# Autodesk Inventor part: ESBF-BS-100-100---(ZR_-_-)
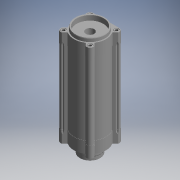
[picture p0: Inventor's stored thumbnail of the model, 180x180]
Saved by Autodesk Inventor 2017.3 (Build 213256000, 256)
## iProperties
Part Number: ESBF-BS-100-100---(ZR_-_-)
Material: Generic
Catalog Web Link: www.cadenas.de
Description: ESBF-(ZR)-Electro-cylinder
Vendor: FESTO
Document SubType Name: Modeling
Designer: partserver
Manufacturer: FESTO
Mass: 2150.83 g
Surface Area: 3014.64 cm^2
Volume: 2150.83 cm^3
Density: 1 g/cm^3
Appearance: PSOLRGB-192-192-192
Category: PARTsolutions
Company: FESTO
Title: ESBF-BS-100-100---(ZR_-_-)
Author: Cadenas PARTsolutions
Comments: Electro-cylinder
PSOL_IDENT_0: {$CADENAS_DATA\23d-libs\festo\parts\e\esbf\parts\esbf_zr.prj},210 {VTYP=3D},{NB=ESBF-BS-100-100---(Z
PSOL_IDENT_1: R_-_-)},{LINA=ESBF-BS-100-100---(ZR_-_-)},{NN=ESBF-(ZR)},{DATE=27.05.2021 13:20:18},{GEOMDATE=27.05.
PSOL_IDENT_2: 2021 13:19:59},{VERSION=},{LINEID=30},{WBVAR=HUB,SCEL,BWE},{WBNUMERIC=HUB}  {NB=ESBF-BS-100-100---(Z
PSOL_IDENT_3: R_-_-)},{LINA=ESBF-BS-100-100---(ZR_-_-)},{KT=DUMMY},{TNR=574092},{TYP=ESBF-BS-100},{KDM=100},{HUB=1
PSOL_IDENT_4: 00},{SCEL=-},{BWE=-},{A=29.000},{ANG=45.000},{B=70.000},{B1=68.000},{BE1=18.000},{BG=17.000},{D1=50.
PSOL_IDENT_5: 000},{D2=24.000},{D2R=15.000},{D3=100.000},{D3R=15.800},{D5=90.000},{E=110.000},{E1=0.000},{EG=20.50
PSOL_IDENT_6: 0},{G=39.000},{G1=39.000},{HE=4.000},{R1=10.500},{R1I=10.000},{R2=107.600},{TG=89.000},{RI=53.250},{
PSOL_IDENT_7: RK=1.500},{T5=16.500},{J2=0.000},{L10=21.000},{L14=30.000},{L16=20.200},{L18=0.000},{L1=33.000},{L2=
PSOL_IDENT_8: 224.000},{L3=39.500},{L7=68.500},{M1=10.000},{PL=0.000},{SW3=6.000},{SWT=25.900},{VA=12.000},{VD=20.
PSOL_IDENT_9: 000},{D100=0.000},{GUA=28.000},{B2=5.000},{D6=51.500},{D7=61.200},{BWE1='-','F1A'}
NB: ESBF-BS-100-100---(ZR_-_-)
NN: ESBF-(ZR)
NT: Electro-cylinder
NBSYN: $TYP.-$HUB.---(ZR_$SCEL._$BWE.)
LINA: ESBF-BS-100-100---(ZR_-_-)
CATALOG: Festo
TNR: 574092
TYP: ESBF-BS-100
KDM: 100
HUB: 100
SCEL: -
BWE: -
A: 29
ANG: 45
B: 70
B1: 68
BE1: 18
BG: 17
D1: 50
D2: 24
D2R: 15
D3: 100
D3R: 15.8
D5: 90
E: 110
E1: 0
EG: 20.5
G: 39
G1: 39
HE: 4
R1: 10.5
R1I: 10
R2: 107.6
TG: 89
RI: 53.25
RK: 1.5
T5: 16.5
J2: 0
L10: 21
L14: 30
L16: 20.2
L18: 0
L1: 33
L2: 224
L3: 39.5
L7: 68.5
M1: 10
PL: 0
SW3: 6
SWT: 25.9
VA: 12
VD: 20
D100: 0
GUA: 28
B2: 5
D6: 51.5
D7: 61.2
SUPPLIER: FESTO
ARTICLENO: ESBF-BS-100-100---(ZR_-_-)
BOMINFO: ESBF-BS-100-100---(ZR_-_-)
CREATOR: CADENAS GmbH
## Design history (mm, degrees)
sketch "Sketch_1"
  geometry: L1 (-54.561, 39.711)-(-45.596, 30.747); L2 (-45.596, -30.747)-(-54.561, -39.711); L3 (-55, -40.772)-(-55, -44.5); L4 (-44.5, -55)-(-40.772, -55); L5 (-39.711, -54.561)-(-30.747, -45.596); L6 (30.747, -45.596)-(39.711, -54.561); L7 (40.772, -55)-(44.5, -55); L8 (55, -44.5)-(55, -40.772); L9 (54.561, -39.711)-(45.596, -30.747); L10 (45.596, 30.747)-(54.561, 39.711); L11 (55, 40.772)-(55, 44.5); L12 (44.5, 55)-(-44.5, 55); L13 (-55, 44.5)-(-55, 40.772); A1 r 1.5 centre (-53.5, 40.772) between (-55, 40.772) and (-54.561, 39.711); A2 r 1.5 centre (-46.657, 29.686) between (-45.391, 28.881) and (-45.596, 30.747); A3 r 53.8 centre (0, 0) between (-45.391, 28.881) and (-45.391, -28.881); A4 r 1.5 centre (-46.657, -29.686) between (-45.596, -30.747) and (-45.391, -28.881); A5 r 1.5 centre (-53.5, -40.772) between (-54.561, -39.711) and (-55, -40.772); A6 r 10.5 centre (-44.5, -44.5) between (-55, -44.5) and (-44.5, -55); A7 r 1.5 centre (-40.772, -53.5) between (-40.772, -55) and (-39.711, -54.561); A8 r 1.5 centre (-29.686, -46.657) between (-28.881, -45.391) and (-30.747, -45.596); A9 r 53.8 centre (0, 0) between (-28.881, -45.391) and (28.881, -45.391); A10 r 1.5 centre (29.686, -46.657) between (30.747, -45.596) and (28.881, -45.391); A11 r 1.5 centre (40.772, -53.5) between (39.711, -54.561) and (40.772, -55); A12 r 10.5 centre (44.5, -44.5) between (44.5, -55) and (55, -44.5); A13 r 1.5 centre (53.5, -40.772) between (55, -40.772) and (54.561, -39.711); A14 r 1.5 centre (46.657, -29.686) between (45.391, -28.881) and (45.596, -30.747); A15 r 53.8 centre (0, 0) between (45.391, -28.881) and (45.391, 28.881); A16 r 1.5 centre (46.657, 29.686) between (45.596, 30.747) and (45.391, 28.881); A17 r 1.5 centre (53.5, 40.772) between (54.561, 39.711) and (55, 40.772); A18 r 10.5 centre (44.5, 44.5) between (55, 44.5) and (44.5, 55); A19 r 10.5 centre (-44.5, 44.5) between (-44.5, 55) and (-55, 44.5)
  constraints: 38 point on circle, 26 end point, 19 centre point
extrude "Extrusion1" join sketch "Sketch_1" distance "d0" = 39; taper "d1" = 0 deg
sketch "Sketch_8"
  geometry: L1 (-50, 73)-(50, 73); L2 (-41.5, 68.75)-(-41.5, 55); L3 (-41.5, 55)-(-39.248, 51.1); L4 (-39.075, 51)-(-38.373, 51); L5 (-38.232, 51.059)-(-34.291, 55); L6 (-34.291, 55)-(34.291, 55); L7 (34.291, 55)-(38.232, 51.059); L8 (38.373, 51)-(39.075, 51); L9 (39.248, 51.1)-(41.5, 55); L10 (41.5, 55)-(41.5, 68.75); L11 (41.5, 68.75)-(-41.5, 68.75); A1 r 0.2 centre (-39.075, 51.2) between (-39.248, 51.1) and (-39.075, 51); A2 r 0.2 centre (-38.373, 51.2) between (-38.373, 51) and (-38.232, 51.059); A3 r 0.2 centre (38.373, 51.2) between (38.232, 51.059) and (38.373, 51); A4 r 0.2 centre (39.075, 51.2) between (39.075, 51) and (39.248, 51.1)
  constraints: 22 end point, 8 point on circle, 4 centre point
revolve "Revolution1" sketch "Sketch_8" stored, may be unused: angle "d2" = 360 deg
sketch "Sketch_21"
  geometry: L1 (50, -74)-(-50, -74); L2 (-41.5, -68.75)-(41.5, -68.75); L3 (41.5, -68.75)-(41.5, -55); L4 (41.5, -55)-(39.248, -51.1); L5 (39.075, -51)-(25.005, -51); L6 (-25.005, -51)-(-39.075, -51); L7 (-39.248, -51.1)-(-41.5, -55); L8 (-41.5, -55)-(-41.5, -68.75); A1 r 0.2 centre (39.075, -51.2) between (39.248, -51.1) and (39.075, -51); A2 r 56.8 centre (0, 0) between (-25.005, -51) and (25.005, -51); A3 r 0.2 centre (-39.075, -51.2) between (-39.075, -51) and (-39.248, -51.1)
  constraints: 16 end point, 6 point on circle, 3 centre point
revolve "Revolution2" sketch "Sketch_21" stored, may be unused: angle "d3" = 360 deg
sketch "Sketch_23"
  geometry: L1 (74, 50)-(74, -50); L2 (51, -25.005)-(51, -39.075); L3 (51.1, -39.248)-(55, -41.5); L4 (55, -41.5)-(68.75, -41.5); L5 (68.75, -41.5)-(68.75, 41.5); L6 (68.75, 41.5)-(55, 41.5); L7 (55, 41.5)-(51.1, 39.248); L8 (51, 39.075)-(51, 25.005); A1 r 0.2 centre (51.2, -39.075) between (51, -39.075) and (51.1, -39.248); A2 r 0.2 centre (51.2, 39.075) between (51.1, 39.248) and (51, 39.075); A3 r 56.8 centre (0, 0) between (51, -25.005) and (51, 25.005)
  constraints: 16 end point, 6 point on circle, 3 centre point
revolve "Revolution3" sketch "Sketch_23" stored, may be unused: angle "d4" = 360 deg
sketch "Sketch_24"
  geometry: L1 (-74, -50)-(-74, 50); L2 (-68.75, -41.5)-(-55, -41.5); L3 (-55, -41.5)-(-51.1, -39.248); L4 (-51, -39.075)-(-51, -25.005); L5 (-51, 25.005)-(-51, 39.075); L6 (-51.1, 39.248)-(-55, 41.5); L7 (-55, 41.5)-(-68.75, 41.5); L8 (-68.75, 41.5)-(-68.75, -41.5); A1 r 0.2 centre (-51.2, -39.075) between (-51.1, -39.248) and (-51, -39.075); A2 r 56.8 centre (0, 0) between (-51, 25.005) and (-51, -25.005); A3 r 0.2 centre (-51.2, 39.075) between (-51, 39.075) and (-51.1, 39.248)
  constraints: 16 end point, 6 point on circle, 3 centre point
revolve "Revolution4" sketch "Sketch_24" stored, may be unused: angle "d5" = 360 deg
sketch "Sketch_41"
  geometry: L1 (0, -285)-(0, -39); L2 (0, -39)-(5, -39); L3 (5, -39)-(5, -285); L4 (5, -285)-(0, -285); L5 (0, -285)-(0, -39)
  constraints: 10 end point
revolve "Revolution5" sketch "Sketch_41" stored, may be unused: angle "d6" = 360 deg
sketch "Sketch_5"
  geometry: L1 (-54.561, 39.711)-(-45.596, 30.747); L2 (-45.596, -30.747)-(-54.561, -39.711); L3 (-55, -40.772)-(-55, -44.5); L4 (-44.5, -55)-(-40.772, -55); L5 (-39.711, -54.561)-(-30.747, -45.596); L6 (30.747, -45.596)-(39.711, -54.561); L7 (40.772, -55)-(44.5, -55); L8 (55, -44.5)-(55, -40.772); L9 (54.561, -39.711)-(45.596, -30.747); L10 (45.596, 30.747)-(54.561, 39.711); L11 (55, 40.772)-(55, 44.5); L12 (44.5, 55)-(-44.5, 55); L13 (-55, 44.5)-(-55, 40.772); A1 r 1.5 centre (-53.5, 40.772) between (-55, 40.772) and (-54.561, 39.711); A2 r 1.5 centre (-46.657, 29.686) between (-45.391, 28.881) and (-45.596, 30.747); A3 r 53.8 centre (0, 0) between (-45.391, 28.881) and (-45.391, -28.881); A4 r 1.5 centre (-46.657, -29.686) between (-45.596, -30.747) and (-45.391, -28.881); A5 r 1.5 centre (-53.5, -40.772) between (-54.561, -39.711) and (-55, -40.772); A6 r 10.5 centre (-44.5, -44.5) between (-55, -44.5) and (-44.5, -55); A7 r 1.5 centre (-40.772, -53.5) between (-40.772, -55) and (-39.711, -54.561); A8 r 1.5 centre (-29.686, -46.657) between (-28.881, -45.391) and (-30.747, -45.596); A9 r 53.8 centre (0, 0) between (-28.881, -45.391) and (28.881, -45.391); A10 r 1.5 centre (29.686, -46.657) between (30.747, -45.596) and (28.881, -45.391); A11 r 1.5 centre (40.772, -53.5) between (39.711, -54.561) and (40.772, -55); A12 r 10.5 centre (44.5, -44.5) between (44.5, -55) and (55, -44.5); A13 r 1.5 centre (53.5, -40.772) between (55, -40.772) and (54.561, -39.711); A14 r 1.5 centre (46.657, -29.686) between (45.391, -28.881) and (45.596, -30.747); A15 r 53.8 centre (0, 0) between (45.391, -28.881) and (45.391, 28.881); A16 r 1.5 centre (46.657, 29.686) between (45.596, 30.747) and (45.391, 28.881); A17 r 1.5 centre (53.5, 40.772) between (54.561, 39.711) and (55, 40.772); A18 r 10.5 centre (44.5, 44.5) between (55, 44.5) and (44.5, 55); A19 r 10.5 centre (-44.5, 44.5) between (-44.5, 55) and (-55, 44.5)
  constraints: 38 point on circle, 26 end point, 19 centre point
extrude "Extrusion2" join sketch "Sketch_5" distance "d7" = 39; taper "d8" = 0 deg
sketch "Sketch_4"
  geometry: L1 (-50, 74)-(50, 74); L2 (-41.5, 68.75)-(-41.5, 55); L3 (-41.5, 55)-(-39.248, 51.1); L4 (-39.075, 51)-(-38.373, 51); L5 (-38.232, 51.059)-(-34.291, 55); L6 (-34.291, 55)-(34.291, 55); L7 (34.291, 55)-(38.232, 51.059); L8 (38.373, 51)-(39.075, 51); L9 (39.248, 51.1)-(41.5, 55); L10 (41.5, 55)-(41.5, 68.75); L11 (41.5, 68.75)-(-41.5, 68.75); A1 r 0.2 centre (-39.075, 51.2) between (-39.248, 51.1) and (-39.075, 51); A2 r 0.2 centre (-38.373, 51.2) between (-38.373, 51) and (-38.232, 51.059); A3 r 0.2 centre (38.373, 51.2) between (38.232, 51.059) and (38.373, 51); A4 r 0.2 centre (39.075, 51.2) between (39.075, 51) and (39.248, 51.1)
  constraints: 22 end point, 8 point on circle, 4 centre point
revolve "Revolution6" sketch "Sketch_4" stored, may be unused: angle "d9" = 360 deg
sketch "Sketch_25"
  geometry: L1 (50, -74)-(-50, -74); L2 (-41.5, -73.333)-(41.5, -73.333); L3 (41.5, -73.333)-(41.5, -55); L4 (41.5, -55)-(39.248, -51.1); L5 (39.075, -51)-(25.005, -51); L6 (-25.005, -51)-(-39.075, -51); L7 (-39.248, -51.1)-(-41.5, -55); L8 (-41.5, -55)-(-41.5, -73.333); A1 r 0.2 centre (39.075, -51.2) between (39.248, -51.1) and (39.075, -51); A2 r 56.8 centre (0, 0) between (-25.005, -51) and (25.005, -51); A3 r 0.2 centre (-39.075, -51.2) between (-39.075, -51) and (-39.248, -51.1)
  constraints: 16 end point, 6 point on circle, 3 centre point
revolve "Revolution7" sketch "Sketch_25" stored, may be unused: angle "d10" = 360 deg
sketch "Sketch_26"
  geometry: L1 (74, 50)-(74, -50); L2 (51, -25.005)-(51, -39.075); L3 (51.1, -39.248)-(55, -41.5); L4 (55, -41.5)-(68.75, -41.5); L5 (68.75, -41.5)-(68.75, 41.5); L6 (68.75, 41.5)-(55, 41.5); L7 (55, 41.5)-(51.1, 39.248); L8 (51, 39.075)-(51, 25.005); A1 r 0.2 centre (51.2, -39.075) between (51, -39.075) and (51.1, -39.248); A2 r 0.2 centre (51.2, 39.075) between (51.1, 39.248) and (51, 39.075); A3 r 56.8 centre (0, 0) between (51, -25.005) and (51, 25.005)
  constraints: 16 end point, 6 point on circle, 3 centre point
revolve "Revolution8" sketch "Sketch_26" stored, may be unused: angle "d11" = 360 deg
sketch "Sketch_27"
  geometry: L1 (-74, -50)-(-74, 50); L2 (-68.75, -41.5)-(-55, -41.5); L3 (-55, -41.5)-(-51.1, -39.248); L4 (-51, -39.075)-(-51, -25.005); L5 (-51, 25.005)-(-51, 39.075); L6 (-51.1, 39.248)-(-55, 41.5); L7 (-55, 41.5)-(-68.75, 41.5); L8 (-68.75, 41.5)-(-68.75, -41.5); A1 r 0.2 centre (-51.2, -39.075) between (-51.1, -39.248) and (-51, -39.075); A2 r 56.8 centre (0, 0) between (-51, 25.005) and (-51, -25.005); A3 r 0.2 centre (-51.2, 39.075) between (-51, 39.075) and (-51.1, 39.248)
  constraints: 16 end point, 6 point on circle, 3 centre point
revolve "Revolution9" sketch "Sketch_27" stored, may be unused: angle "d12" = 360 deg
sketch "Sketch_43"
  geometry: L1 (-41.679, -54.155)-(-39.828, -50.95); L2 (-39.482, -50.75)-(-36.42, -50.75); L3 (-36.137, -50.633)-(-30.564, -45.06); L4 (30.564, -45.06)-(36.137, -50.633); L5 (36.42, -50.75)-(39.482, -50.75); L6 (39.828, -50.95)-(41.679, -54.155); L7 (54.155, -41.679)-(50.95, -39.828); L8 (50.75, -39.482)-(50.75, -36.42); L9 (50.633, -36.137)-(45.06, -30.564); L10 (44.197, 29.701)-(50.633, 36.137); L11 (50.75, 36.42)-(50.75, 39.482); L12 (50.95, 39.828)-(54.155, 41.679); L13 (41.679, 54.155)-(39.828, 50.95); L14 (39.482, 50.75)-(38.871, 50.75); L15 (37.811, 51.189)-(34.25, 54.75); L16 (34.25, 54.75)-(-34.25, 54.75); L17 (-34.25, 54.75)-(-37.811, 51.189); L18 (-38.871, 50.75)-(-39.482, 50.75); L19 (-39.828, 50.95)-(-41.679, 54.155); L20 (-54.155, 41.679)-(-50.95, 39.828); L21 (-50.75, 39.482)-(-50.75, 36.42); L22 (-50.633, 36.137)-(-44.197, 29.701); L23 (-45.06, -30.564)-(-50.633, -36.137); L24 (-50.75, -36.42)-(-50.75, -39.482); L25 (-50.95, -39.828)-(-54.155, -41.679); A1 r 10 centre (-44.75, -44.75) between (-54.339, -41.912) and (-41.912, -54.339); A2 r 0.4 centre (-42.025, -53.955) between (-41.912, -54.339) and (-41.679, -54.155); A3 r 0.4 centre (-39.482, -51.15) between (-39.482, -50.75) and (-39.828, -50.95); A4 r 0.4 centre (-36.42, -50.35) between (-36.42, -50.75) and (-36.137, -50.633); A5 r 1.5 centre (-29.504, -46.121) between (-28.695, -44.857) and (-30.564, -45.06); A6 r 53.25 centre (0, 0) between (-28.695, -44.857) and (28.695, -44.857); A7 r 1.5 centre (29.504, -46.121) between (30.564, -45.06) and (28.695, -44.857); A8 r 0.4 centre (36.42, -50.35) between (36.137, -50.633) and (36.42, -50.75); A9 r 0.4 centre (39.482, -51.15) between (39.828, -50.95) and (39.482, -50.75); A10 r 0.4 centre (42.025, -53.955) between (41.679, -54.155) and (41.912, -54.339); A11 r 10 centre (44.75, -44.75) between (41.912, -54.339) and (54.339, -41.912); A12 r 0.4 centre (53.955, -42.025) between (54.339, -41.912) and (54.155, -41.679); A13 r 0.4 centre (51.15, -39.482) between (50.75, -39.482) and (50.95, -39.828); A14 r 0.4 centre (50.35, -36.42) between (50.75, -36.42) and (50.633, -36.137); A15 r 1.5 centre (46.121, -29.504) between (44.857, -28.695) and (45.06, -30.564); A16 r 53.25 centre (0, 0) between (44.857, -28.695) and (44.197, 29.701); A17 r 0.4 centre (50.35, 36.42) between (50.633, 36.137) and (50.75, 36.42); A18 r 0.4 centre (51.15, 39.482) between (50.95, 39.828) and (50.75, 39.482); A19 r 0.4 centre (53.955, 42.025) between (54.155, 41.679) and (54.339, 41.912); A20 r 10 centre (44.75, 44.75) between (54.339, 41.912) and (41.912, 54.339); A21 r 0.4 centre (42.025, 53.955) between (41.912, 54.339) and (41.679, 54.155); A22 r 0.4 centre (39.482, 51.15) between (39.482, 50.75) and (39.828, 50.95); A23 r 1.5 centre (38.871, 52.25) between (37.811, 51.189) and (38.871, 50.75); A24 r 1.5 centre (-38.871, 52.25) between (-38.871, 50.75) and (-37.811, 51.189); A25 r 0.4 centre (-39.482, 51.15) between (-39.828, 50.95) and (-39.482, 50.75); A26 r 0.4 centre (-42.025, 53.955) between (-41.679, 54.155) and (-41.912, 54.339); A27 r 10 centre (-44.75, 44.75) between (-41.912, 54.339) and (-54.339, 41.912); A28 r 0.4 centre (-53.955, 42.025) between (-54.339, 41.912) and (-54.155, 41.679); A29 r 0.4 centre (-51.15, 39.482) between (-50.75, 39.482) and (-50.95, 39.828); A30 r 0.4 centre (-50.35, 36.42) between (-50.75, 36.42) and (-50.633, 36.137); A31 r 53.25 centre (0, 0) between (-44.197, 29.701) and (-44.857, -28.695); A32 r 1.5 centre (-46.121, -29.504) between (-45.06, -30.564) and (-44.857, -28.695); A33 r 0.4 centre (-50.35, -36.42) between (-50.633, -36.137) and (-50.75, -36.42); A34 r 0.4 centre (-51.15, -39.482) between (-50.95, -39.828) and (-50.75, -39.482); A35 r 0.4 centre (-53.955, -42.025) between (-54.155, -41.679) and (-54.339, -41.912)
  constraints: 70 point on circle, 50 end point, 35 centre point
extrude "Extrusion3" join sketch "Sketch_43" distance "d13" = 246; taper "d14" = 0 deg
sketch "Sketch_3"
  geometry: L1 (0, 0)-(0, 38); L2 (0, 38)-(25.75, 38); L3 (26.656, 36.325)-(30.6, 33.75); L4 (30.6, 33.75)-(30.6, 33); L5 (30.6, 33)-(33.5, 33); L6 (33.5, 33)-(34, 32.5); L7 (34, 32.5)-(34, 21.732); L8 (34, 21.732)-(35, 20); L9 (35, 20)-(35, 0); L10 (35, 0)-(0, 0); L11 (0, 0)-(0, 38); A1 r 2 centre (27.75, 38) between (25.75, 38) and (26.656, 36.325)
  constraints: 22 end point, 2 point on circle, 1 centre point
revolve "Revolution10" sketch "Sketch_3" stored, may be unused: angle "d15" = 360 deg
sketch "Sketch_45"
  geometry: L1 (0, 54.45)-(0, 54.75); L2 (0, 54.75)-(7.05, 54.75); L3 (7.05, 54.75)-(7.05, 54.45); L4 (7.05, 54.45)-(0, 54.45); L5 (0, 54.45)-(0, 54.75)
  constraints: 10 end point
revolve "Revolution11" sketch "Sketch_45" stored, may be unused: angle "d16" = 360 deg
sketch "Sketch_9"
  geometry: L1 (30, 44.5)-(0, 44.5); L2 (0, 44.5)-(0, 52.4); L3 (0, 52.4)-(30, 52.4); L4 (30, 52.4)-(30, 44.5); L5 (30, 44.5)-(0, 44.5)
  constraints: 10 end point
revolve "Revolution12" sketch "Sketch_9" stored, may be unused: angle "d17" = 360 deg
pattern_linear "Rectangular Pattern1" dims "d20" = 89, "d23" = 89
sketch "Sketch_11"
  geometry: L1 (30, 44.5)-(0, 44.5); L2 (0, 44.5)-(0, 51); L3 (0, 51)-(1, 52); L4 (1, 52)-(30, 52); L5 (30, 52)-(30, 44.5); L6 (30, 44.5)-(0, 44.5)
  constraints: 12 end point
revolve "Revolution13" sketch "Sketch_11" stored, may be unused: angle "d24" = 360 deg
pattern_linear "Rectangular Pattern2" dims "d27" = 89, "d30" = 89
sketch "Sketch_17"
  geometry: L1 (22.258, 44.5)-(0, 44.5); L2 (0, 44.5)-(0, 49.5); L3 (0, 49.5)-(0.812, 48.688); L4 (0.812, 48.688)-(20.2, 48.688); L5 (20.2, 48.688)-(22.258, 47.5); L6 (22.258, 47.5)-(22.258, 44.5); L7 (22.258, 44.5)-(0, 44.5)
  constraints: 14 end point
revolve "Revolution14" sketch "Sketch_17" stored, may be unused: angle "d31" = 360 deg
thread "Thread1" dims "d32" = 16.188, "d33" = 0
sketch "Sketch_18"
  geometry: L1 (41.5, 42.768)-(44.5, 41.036); L2 (44.5, 41.036)-(47.5, 42.768); L3 (47.5, 42.768)-(47.5, 46.232); L4 (47.5, 46.232)-(44.5, 47.964); L5 (44.5, 47.964)-(41.5, 46.232); L6 (41.5, 46.232)-(41.5, 42.768)
  constraints: 12 end point
extrude "Extrusion4" cut sketch "Sketch_18" distance "d34" = 25.9; taper "d35" = 0 deg
pattern_linear "Rectangular Pattern3" dims "d38" = 89, "d41" = 89
pattern_linear "Rectangular Pattern4" dims "d44" = 89, "d47" = 89
sketch "Sketch_22"
  geometry: L1 (0, -336)-(0, -324); L2 (0, -324)-(50, -324); L3 (50, -324)-(50, -334); L4 (50, -334)-(49.272, -336); L5 (49.272, -336)-(0, -336); L6 (0, -336)-(0, -324)
  constraints: 12 end point
revolve "Revolution15" sketch "Sketch_22" stored, may be unused: angle "d48" = 360 deg
sketch "Sketch_2"
  geometry: L1 (0, -336)-(0, -285); L2 (0, -285)-(14, -285); L3 (14, -285)-(14, -319.5); L4 (14, -319.5)-(45, -319.5); L5 (45, -319.5)-(45, -335); L6 (45, -335)-(45.364, -336); L7 (45.364, -336)-(0, -336); L8 (0, -336)-(0, -285)
  constraints: 16 end point
revolve "Revolution16" sketch "Sketch_2" stored, may be unused: angle "d49" = 360 deg
sketch "Sketch21"
  geometry: 1 further point
hole "Hole1" sketch "Sketch21" at (-44.5, 44.5) diameter "d50" = 15.8; stored, may be unused: countersink angle "d54" = 90 deg, drill point angle "d56" = 0 deg; dims "d51" = 6, "d52" = 4, "d53" = 2, "d55" = 30
pattern_linear "Rectangular Pattern5" dims "d59" = 89, "d62" = 89
sketch "Sketch_30"
  geometry: L1 (324, 44.5)-(294, 44.5); L2 (294, 44.5)-(294, 52); L3 (294, 52)-(323, 52); L4 (323, 52)-(324, 51); L5 (324, 51)-(324, 44.5); L6 (324, 44.5)-(294, 44.5)
  constraints: 12 end point
revolve "Revolution17" sketch "Sketch_30" stored, may be unused: angle "d63" = 360 deg
pattern_linear "Rectangular Pattern6" dims "d66" = 89, "d69" = 89
sketch "Sketch_36"
  geometry: L1 (324, 44.5)-(301.742, 44.5); L2 (301.742, 44.5)-(301.742, 47.5); L3 (301.742, 47.5)-(303.8, 48.688); L4 (303.8, 48.688)-(323.188, 48.688); L5 (323.188, 48.688)-(324, 49.5); L6 (324, 49.5)-(324, 44.5); L7 (324, 44.5)-(301.742, 44.5)
  constraints: 14 end point
revolve "Revolution18" sketch "Sketch_36" stored, may be unused: angle "d70" = 360 deg
thread "Thread2" dims "d71" = 16.188, "d72" = 0
pattern_linear "Rectangular Pattern7" dims "d75" = 89, "d78" = 89
sketch "Sketch_38"
  geometry: L1 (41.5, 42.768)-(44.5, 41.036); L2 (44.5, 41.036)-(47.5, 42.768); L3 (47.5, 42.768)-(47.5, 46.232); L4 (47.5, 46.232)-(44.5, 47.964); L5 (44.5, 47.964)-(41.5, 46.232); L6 (41.5, 46.232)-(41.5, 42.768)
  constraints: 12 end point
extrude "Extrusion5" cut sketch "Sketch_38" distance "d79" = 25.9; taper "d80" = 0 deg
pattern_linear "Rectangular Pattern8" dims "d83" = 89, "d86" = 89
sketch "Sketch25"
  geometry: 1 further point
hole "Hole2" sketch "Sketch25" at (0, 0) diameter "d87" = 50; stored, may be unused: countersink angle "d91" = 90 deg, drill point angle "d93" = 0 deg; dims "d88" = 6, "d89" = 100, "d90" = 133.33333, "d92" = 323
node "GUA_XY"
node "GUA_YZ"
node "GUA_ZX"
node "GUA_X"
node "GUA_Y"
node "GUA_Z"
node "GUA_Center"
node "KS_XY"
node "KS_YZ"
node "KS_ZX"
node "KS_X"
node "KS_Y"
node "KS_Z"
node "KS_Center"
node "KSA_XY"
node "KSA_YZ"
node "KSA_ZX"
node "KSA_X"
node "KSA_Y"
node "KSA_Z"
node "KSA_Center"
node "PLUG_XY"
node "PLUG_YZ"
node "PLUG_ZX"
node "PLUG_X"
node "PLUG_Y"
node "PLUG_Z"
node "PLUG_Center"
node "SENSOR_XY"
node "SENSOR_YZ"
node "SENSOR_ZX"
node "SENSOR_X"
node "SENSOR_Y"
node "SENSOR_Z"
node "SENSOR_Center"
node "START_XY"
node "START_YZ"
node "START_ZX"
node "START_X"
node "START_Y"
node "START_Z"
node "START_Center"
body "Solid1"
other parameters: "d94" = 0, "d95" = 0, "d96" = 0, "d97" = 0, "d98" = 0
